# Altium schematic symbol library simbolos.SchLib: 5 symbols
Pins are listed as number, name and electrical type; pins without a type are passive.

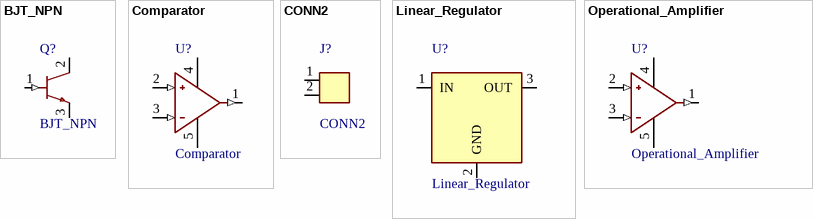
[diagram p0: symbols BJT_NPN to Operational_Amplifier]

## BJT_NPN
designator Q?
Conceptual NPN B/C/E; not a device pinout
pins: 1 B (in), 2 C, 3 E

## Comparator
designator U?
Conceptual comparator; not a device pinout
pins: 1 (out), 2 + (in), 3 - (in), 4 V+ (power), 5 V- (power)

## CONN2
designator J?
Two-pin connector, pins on the left. Fenolite example symbol
pins: 1, 2

## Linear_Regulator
designator U?
Conceptual three-function linear regulator; not a device pinout
pins: 1 IN (power), 2 GND (power), 3 OUT (power)

## Operational_Amplifier
designator U?
Conceptual five-function op amp; not a device pinout
pins: 1 (out), 2 + (in), 3 - (in), 4 V+ (power), 5 V- (power)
